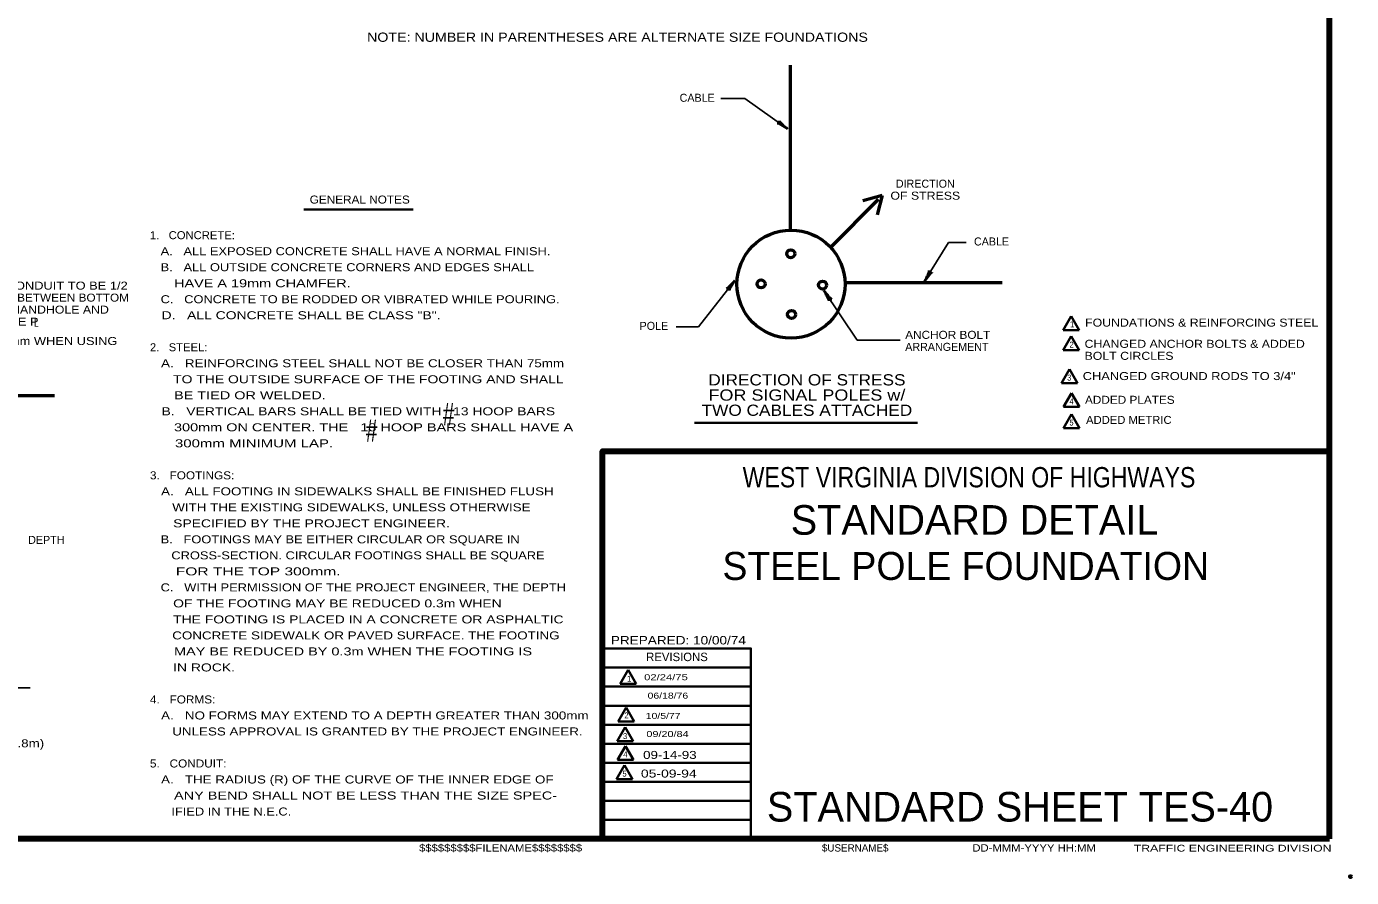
# Model space of a CAD drawing. Extents: x -711 to 145, y 25 to 569.
# Drawn here: x -252.6 to 144.7, y 25 to 280.2 of the extents above; entities that cross this region are included whole.
import ezdxf
from ezdxf.enums import TextEntityAlignment as Align

# ---------------------------------------------------------------- set-up
doc = ezdxf.new("R2010")
doc.units = 0
doc.header["$LTSCALE"] = 1.1
doc.header["$PDMODE"] = 32
doc.header["$PDSIZE"] = 0.55
doc.layers.add('1', color=7, linetype='Continuous', lineweight=53)
doc.layers.add('61', color=7, linetype='Continuous', lineweight=35)

msp = doc.modelspace()

# ---------------------------------------------------------------- linework, layer by layer
at = {"layer": '1', "lineweight": 158}
for q in [(138.105, 562.675), (138.105, 152.875), (-653.495, 36.575)]:
    msp.add_line((138.105, 36.575), q, dxfattribs=at)
at = {"layer": '1', "lineweight": 13}
msp.add_line((138.105, 36.575), (138.105, 562.675), dxfattribs=at)
at = {"layer": '1'}
for p, q in [((-23.595, 268.603), (-23.595, 219.403)), ((-11.499, 213.945), (2.902, 228.346)), ((3.967, 229.481), (-1.828, 227.928)), ((3.967, 229.481), (2.414, 223.685)), ((-6.882, 203.377), (39.918, 203.377)), ((-263.611, 169.492), (-244.167, 169.492))]:
    msp.add_line(p, q, dxfattribs=at)
at = {"layer": '1', "lineweight": 25}
for p, q in [((-37.174, 258.565), (-44.44, 258.565)), ((-24.407, 249.512), (-37.174, 258.565)), ((16.678, 203.784), (23.874, 215.39)), ((23.874, 215.39), (29.13, 215.39)), ((-40.192, 204.016), (-51.101, 190.089)), ((-51.101, 190.089), (-57.845, 190.089)), ((-277.909, 81.866), (-251.509, 81.866))]:
    msp.add_line(p, q, dxfattribs=at)
at = {"layer": '1', "lineweight": 35}
for p, q in [((-169.445, 225.242), (-136.64, 225.242)), ((60.64, 193.265), (58.24, 189.108)), ((60.64, 193.265), (63.04, 189.108)), ((58.24, 189.108), (63.04, 189.108)), ((60.64, 187.287), (58.24, 183.13)), ((60.64, 187.287), (63.04, 183.13)), ((58.24, 183.13), (63.04, 183.13)), ((60.085, 177.395), (57.685, 173.238)), ((60.085, 177.395), (62.485, 173.238)), ((57.685, 173.238), (62.485, 173.238)), ((60.765, 170.269), (58.365, 166.113)), ((60.765, 170.269), (63.165, 166.113)), ((58.365, 166.113), (63.165, 166.113)), ((60.765, 163.926), (58.365, 159.769)), ((60.765, 163.926), (63.165, 159.769)), ((-52.262, 161.306), (14.589, 161.306)), ((58.365, 159.769), (63.165, 159.769)), ((-35.395, 87.975), (-79.895, 87.975)), ((-72.21, 87.255), (-74.61, 83.098)), ((-72.21, 87.255), (-69.81, 83.098)), ((-35.395, 82.275), (-79.895, 82.275)), ((-74.61, 83.098), (-69.81, 83.098)), ((-35.395, 76.475), (-79.895, 76.475)), ((-72.81, 75.967), (-75.21, 71.81)), ((-72.81, 75.967), (-70.41, 71.81)), ((-75.21, 71.81), (-70.41, 71.81)), ((-35.395, 70.775), (-79.895, 70.775)), ((-73.077, 70.068), (-75.477, 65.911)), ((-73.077, 70.068), (-70.677, 65.911)), ((-35.395, 65.075), (-79.895, 65.075)), ((-75.477, 65.911), (-70.677, 65.911)), ((-73.002, 64.397), (-75.401, 60.24)), ((-73.002, 64.397), (-70.602, 60.24)), ((-75.401, 60.24), (-70.602, 60.24)), ((-35.395, 59.375), (-79.895, 59.375)), ((-73.249, 58.65), (-75.649, 54.493)), ((-73.249, 58.65), (-70.849, 54.493)), ((-35.395, 53.675), (-79.895, 53.675)), ((-75.649, 54.493), (-70.849, 54.493)), ((-35.395, 47.975), (-79.895, 47.975)), ((-35.395, 42.275), (-79.895, 42.275))]:
    msp.add_line(p, q, dxfattribs=at)
at = {"layer": '1', "lineweight": 25}
msp.add_lwpolyline([(-13.498, 200.999), (-3.517, 186.143), (9.326, 186.143)], dxfattribs=at)
at = {"layer": '1', "lineweight": 158}
msp.add_lwpolyline([(-79.895, 36.575), (-79.895, 152.875), (138.105, 152.875)], dxfattribs=at)
at = {"layer": '1', "lineweight": 35}
msp.add_lwpolyline([(-35.395, 36.575), (-35.395, 93.675), (-79.895, 93.675)], dxfattribs=at)
at = {"layer": '1'}
for centre, radius in [((-23.363, 202.913), 16.2), ((-23.446, 212.028), 1.2), ((-32.346, 202.966), 1.2), ((-13.899, 202.643), 1.2), ((-23.203, 193.823), 1.2)]:
    msp.add_circle(centre, radius, dxfattribs=at)
at = {"layer": '1', "lineweight": 40}
for centre, major_axis, ratio, start_param, end_param in [((-25.667, 249.999), (1.856, -1.087), 0.122415, 0.8963533, 3.1415927), ((-25.357, 250.497), (-1.597, 1.391), 0.07063, 6.2823074, 8.5597026), ((17.086, 205.072), (-0.97, -1.92), 0.122415, 0.8963533, 3.1415927), ((-41.221, 203.114), (-1.466, -1.529), 0.07063, 6.2823074, 8.5597026), ((-40.738, 202.781), (1.174, 1.802), 0.122415, 0.8963533, 3.1415927), ((17.602, 204.793), (1.29, 1.68), 0.07063, 6.2823074, 8.5597026), ((-12.959, 199.741), (1.001, -1.867), 0.07063, 6.2823074, 8.5597026), ((-12.492, 200.097), (-1.351, 1.674), 0.122415, 0.8963533, 3.1415927)]:
    msp.add_ellipse(centre, major_axis=major_axis, ratio=ratio, start_param=start_param, end_param=end_param, dxfattribs=at)
at = {"layer": '1'}
msp.add_point((144.405, 25.275), dxfattribs=at)
at = {"layer": '61', "lineweight": 53}
for q in [(-14.595, 36.575), (-14.595, 36.575), (-14.595, 36.575), (-14.295, 36.575), (-14.295, 36.575)]:
    msp.add_line((138.105, 36.575), q, dxfattribs=at)

# ---------------------------------------------------------------- texts
at = {"layer": '1'}
for s, height, width, p in [('NOTE: NUMBER IN PARENTHESES ARE ALTERNATE SIZE FOUNDATIONS', 2.772, 1.15, (-75.393, 275.571)), ('OF STRESS', 2.4, 1.15, (16.899, 228.234)), ('DIRECTION OF STRESS', 3.36, 1.15, (-18.604, 172.542)), ('FOR SIGNAL POLES w/', 3.36, 1.2, (-18.604, 167.982)), ('#', 6.653, 0.7, (-126.046, 160.609)), ('TWO CABLES ATTACHED', 3.36, 1.15, (-18.604, 163.422)), ('#', 6.653, 0.7, (-149.128, 155.636)), ('WEST VIRGINIA DIVISION OF HIGHWAYS', 6.089, 0.85, (30.005, 141.975)), ('09-14-93 ', 2.4, 1.25, (-59.133, 60.553)), ('05-09-94', 2.4, 1.3, (-60.015, 54.965))]:
    msp.add_text(s, height=height, dxfattribs=dict(at, width=width)).set_placement(p, align=Align.CENTER)
for s, p in [('CABLE', (-46.239, 257.596)), ('CABLE', (42.018, 214.502)), ('POLE', (-60.2, 189.201))]:
    msp.add_text(s, height=2.4, dxfattribs=at).set_placement(p, align=Align.RIGHT)
for s, height, p in [('DIRECTION', 2.4, (16.899, 231.834)), ('STANDARD DETAIL', 8.881, (31.655, 127.775)), ('STEEL POLE FOUNDATION', 8.391, (29.024, 114.218))]:
    msp.add_text(s, height=height, dxfattribs=at).set_placement(p, align=Align.CENTER)
for s, height, width, p in [('GENERAL NOTES', 2.4, 1.1, (-167.681, 227.068)), ('1.   CONCRETE:', 2.4, 1.05, (-215.576, 216.386)), ('   A.   ALL EXPOSED CONCRETE SHALL HAVE A NORMAL FINISH.', 2.4, 1.2, (-215.576, 211.586)), ('   B.   ALL OUTSIDE CONCRETE CORNERS AND EDGES SHALL', 2.4, 1.2, (-215.576, 206.786)), ('TOP OF CONDUIT TO BE 1/2', 2.4, 1.2, (-274.232, 201.268)), ('      HAVE A 19mm CHAMFER.', 2.4, 1.35, (-215.576, 201.986)), ('DISTANCE BETWEEN BOTTOM', 2.4, 1.1, (-274.232, 197.668)), ('   C.   CONCRETE TO BE RODDED OR VIBRATED WHILE POURING.', 2.4, 1.2, (-215.576, 197.186)), ('OF POLE HANDHOLE AND', 2.4, 1.15, (-274.232, 194.068)), ('   D.   ALL CONCRETE SHALL BE CLASS "B".', 2.4, 1.3, (-215.576, 192.386)), ('POLE BASE P', 2.4, 1.2, (-274.232, 190.468)), ('L', 2.4, 0.75, (-250.297, 190.129)), ('FOUNDATIONS & REINFORCING STEEL', 2.4, 1.15, (64.809, 190.176)), ('EXCEPT USE 75mm WHEN USING', 2.4, 1.2, (-287.602, 184.657)), ('ANCHOR BOLT', 2.4, 1.1, (10.875, 186.511)), ('2.   STEEL:', 2.4, 1.05, (-215.576, 182.786)), ('2', 1.8, 0.9, (60.133, 183.875)), ('CHANGED ANCHOR BOLTS & ADDED', 2.4, 1.15, (64.653, 183.817)), ('   A.   REINFORCING STEEL SHALL NOT BE CLOSER THAN 75mm', 2.4, 1.25, (-215.576, 177.986)), ('BOLT CIRCLES', 2.4, 1.15, (64.653, 180.216)), ('      TO THE OUTSIDE SURFACE OF THE FOOTING AND SHALL', 2.4, 1.3, (-215.576, 173.186)), ('3', 1.8, 0.9, (59.423, 173.983)), ('CHANGED GROUND RODS TO 3/4"', 2.4, 1.2, (64.099, 174.15)), ('      BE TIED OR WELDED.', 2.4, 1.35, (-215.576, 168.386)), ('4', 1.8, 0.95, (60.102, 166.857)), ('ADDED PLATES', 2.4, 1.1, (64.778, 167.025)), ('   B.   VERTICAL BARS SHALL BE TIED WITH   13 HOOP BARS', 2.4, 1.3, (-215.576, 163.586)), ('ADDED METRIC', 2.4, 1.05, (65.095, 160.999)), ('      300mm ON CENTER. THE   13 HOOP BARS SHALL HAVE A', 2.4, 1.35, (-215.576, 158.786)), ('5', 1.8, 0.9, (60.102, 160.514)), ('      300mm MINIMUM LAP.', 2.4, 1.4, (-215.576, 153.986)), ('3.   FOOTINGS:', 2.4, 1.1, (-215.576, 144.386)), ('   A.   ALL FOOTING IN SIDEWALKS SHALL BE FINISHED FLUSH', 2.4, 1.25, (-215.576, 139.586)), ('      WITH THE EXISTING SIDEWALKS, UNLESS OTHERWISE', 2.4, 1.25, (-215.576, 134.786)), ('      SPECIFIED BY THE PROJECT ENGINEER.', 2.4, 1.3, (-215.576, 129.986)), ('   B.   FOOTINGS MAY BE EITHER CIRCULAR OR SQUARE IN', 2.4, 1.2, (-215.576, 125.186)), ('      CROSS-SECTION. CIRCULAR FOOTINGS SHALL BE SQUARE', 2.4, 1.2, (-215.576, 120.386)), ('      FOR THE TOP 300mm.', 2.4, 1.45, (-215.576, 115.586)), ('   C.   WITH PERMISSION OF THE PROJECT ENGINEER, THE DEPTH', 2.4, 1.2, (-215.576, 110.786)), ('      OF THE FOOTING MAY BE REDUCED 0.3m WHEN', 2.4, 1.3, (-215.576, 105.986)), ('      THE FOOTING IS PLACED IN A CONCRETE OR ASPHALTIC', 2.4, 1.3, (-215.576, 101.186)), ('      CONCRETE SIDEWALK OR PAVED SURFACE. THE FOOTING', 2.4, 1.25, (-215.576, 96.386)), ('PREPARED: 10/00/74', 2.537, 1.2, (-77.395, 94.875)), ('      MAY BE REDUCED BY 0.3m WHEN THE FOOTING IS', 2.4, 1.35, (-215.576, 91.586)), ('      IN ROCK.', 2.4, 1.3, (-215.576, 86.786)), ('02/24/75', 1.8, 1.4, (-67.418, 84.155)), ('4.   FORMS:', 2.4, 1.1, (-215.576, 77.186)), ('06/18/76', 1.8, 1.3, (-66.372, 78.632)), ('   A.   NO FORMS MAY EXTEND TO A DEPTH GREATER THAN 300mm', 2.4, 1.25, (-215.576, 72.386)), ('2', 1.8, 0.9, (-73.317, 72.711)), ('10/5/77', 1.8, 1.3, (-66.926, 72.555)), ('      UNLESS APPROVAL IS GRANTED BY THE PROJECT ENGINEER.', 2.4, 1.25, (-215.576, 67.586)), ('3', 1.8, 0.9, (-73.739, 66.5)), ('09/20/84', 1.8, 1.35, (-66.725, 67.124)), ('(19.05mmxDEPTH   1.8m)', 2.4, 1.25, (-294.535, 64.038)), ('5.   CONDUIT:', 2.4, 1.1, (-215.576, 57.986)), ('4', 1.8, 0.95, (-73.664, 60.985)), ('   A.   THE RADIUS (R) OF THE CURVE OF THE INNER EDGE OF', 2.4, 1.25, (-215.576, 53.186)), ('5', 1.8, 0.9, (-73.912, 55.238)), ('      ANY BEND SHALL NOT BE LESS THAN THE SIZE SPEC-', 2.4, 1.35, (-215.576, 48.386)), ('      IFIED IN THE N.E.C.   ', 2.4, 1.2, (-215.576, 43.586)), ('$$$$$$$$$FILENAME$$$$$$$$', 2.2, 1.15, (-134.895, 32.775)), ('DD-MMM-YYYY HH:MM', 2.2, 1.15, (31.005, 32.775)), ('TRAFFIC ENGINEERING DIVISION', 2.031, 1.35, (79.405, 32.775))]:
    msp.add_text(s, height=height, dxfattribs=dict(at, width=width)).set_placement(p)
for s, height, p in [('1', 1.8, (60.289, 190.009)), ('ARRANGEMENT', 2.4, (10.875, 182.911)), ('DEPTH', 2.4, (-252.084, 125.035)), ('REVISIONS', 2.537, (-66.795, 89.875)), ('1', 1.8, (-72.561, 83.688)), ('STANDARD SHEET TES-40', 8.881, (-30.595, 41.775)), ('$USERNAME$', 2.2, (-14.095, 32.775))]:
    msp.add_text(s, height=height, dxfattribs=at).set_placement(p)

doc.saveas('drawing.dxf')
